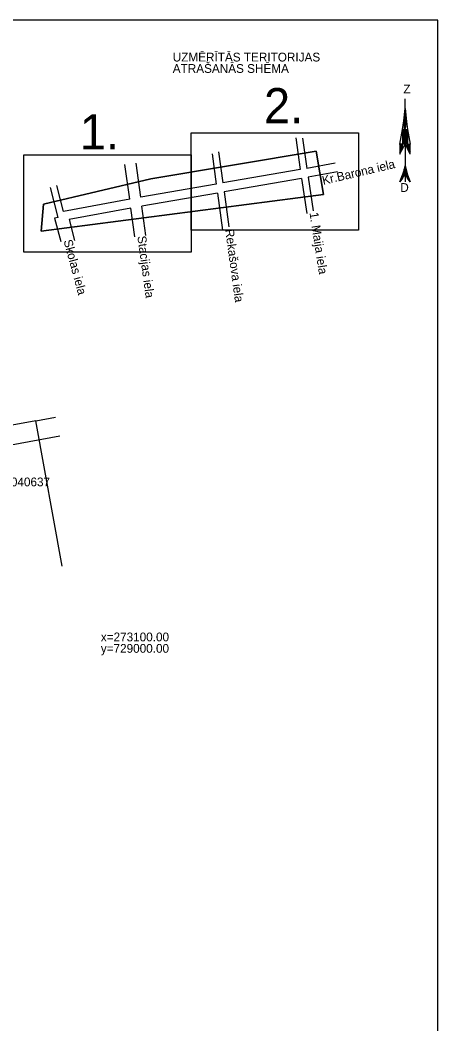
# Model space of a CAD drawing. Extents: x 728492 to 729038, y 272968 to 273171.
# Drawn here: x 728990.8 to 729038.4, y 273056.6 to 273170.9 of the extents above; entities that cross this region are included whole.
import ezdxf

# ---------------------------------------------------------------- set-up
doc = ezdxf.new("R2010")
doc.units = 0
for name, color, linetype in [('APGR_SARK_####_####_#', 7, 'Continuous'), ('GEOD_KORD_####_TKST_#', 7, 'Continuous'), ('RAMI_PLAN_####_TKST_#', 7, 'Continuous'), ('ROBZ_KADS_####_TKST_#', 7, 'Continuous'), ('ROBZ_UZMR_####_####_#', 7, 'Continuous')]:
    doc.layers.add(name, color=color, linetype=linetype)

msp = doc.modelspace()

# ---------------------------------------------------------------- linework, layer by layer
at = {"layer": 'APGR_SARK_####_####_#'}
msp.add_lwpolyline([(728995.34, 273123.52), (728976.64, 273120.07)], dxfattribs=at)
at = {"layer": 'RAMI_PLAN_####_TKST_#'}
for p, q in [((729034.65, 273160.85), (729034.65, 273161.96)), ((729034.49, 273159.46), (729034.65, 273160.85)), ((729034.6, 273160.47), (729034.69, 273160.38)), ((729034.6, 273160.43), (729034.7, 273160.33)), ((729034.6, 273160.39), (729034.7, 273160.28)), ((729034.61, 273160.55), (729034.68, 273160.48)), ((729034.61, 273160.51), (729034.69, 273160.43)), ((729034.62, 273160.63), (729034.67, 273160.58)), ((729034.62, 273160.59), (729034.68, 273160.53)), ((729034.63, 273160.71), (729034.66, 273160.68)), ((729034.63, 273160.67), (729034.67, 273160.63)), ((729034.64, 273160.79), (729034.65, 273160.78)), ((729034.64, 273160.75), (729034.66, 273160.73)), ((729034.65, 273160.85), (729034.8, 273159.38)), ((729034.37, 273158.45), (729034.49, 273159.46)), ((729034.49, 273159.46), (729034.76, 273159.19)), ((729034.63, 273158.45), (729034.49, 273159.46)), ((729034.5, 273159.54), (729034.78, 273159.26)), ((729034.5, 273159.5), (729034.77, 273159.22)), ((729034.5, 273159.41), (729034.76, 273159.15)), ((729034.51, 273159.62), (729034.79, 273159.34)), ((729034.51, 273159.58), (729034.78, 273159.3)), ((729034.51, 273159.35), (729034.75, 273159.11)), ((729034.52, 273159.74), (729034.79, 273159.48)), ((729034.52, 273159.7), (729034.79, 273159.43)), ((729034.52, 273159.66), (729034.8, 273159.38)), ((729034.52, 273159.3), (729034.74, 273159.07)), ((729034.52, 273159.25), (729034.74, 273159.03)), ((729034.53, 273159.82), (729034.78, 273159.58)), ((729034.53, 273159.78), (729034.78, 273159.53)), ((729034.54, 273159.9), (729034.77, 273159.68)), ((729034.54, 273159.86), (729034.77, 273159.63)), ((729034.55, 273159.98), (729034.76, 273159.78)), ((729034.55, 273159.94), (729034.76, 273159.73)), ((729034.56, 273160.1), (729034.74, 273159.93)), ((729034.56, 273160.06), (729034.75, 273159.88)), ((729034.56, 273160.02), (729034.75, 273159.83)), ((729034.57, 273160.18), (729034.73, 273160.03)), ((729034.57, 273160.14), (729034.74, 273159.98)), ((729034.58, 273160.27), (729034.72, 273160.13)), ((729034.58, 273160.23), (729034.73, 273160.08)), ((729034.59, 273160.35), (729034.71, 273160.23)), ((729034.59, 273160.31), (729034.71, 273160.18)), ((729034.8, 273159.38), (729034.63, 273158.45)), ((729034.8, 273159.38), (729034.92, 273158.45)), ((729034.04, 273156.78), (729034.37, 273158.45)), ((729034.37, 273158.45), (729034.36, 273156.81)), ((729034.37, 273158.43), (729034.39, 273158.45)), ((729034.37, 273158.39), (729034.44, 273158.45)), ((729034.37, 273158.34), (729034.48, 273158.45)), ((729034.37, 273158.3), (729034.52, 273158.45)), ((729034.37, 273158.25), (729034.57, 273158.45)), ((729034.37, 273158.21), (729034.61, 273158.45)), ((729034.63, 273158.45), (729034.37, 273158.45)), ((729034.37, 273158.16), (729034.63, 273158.43)), ((729034.37, 273158.12), (729034.63, 273158.38)), ((729034.37, 273158.07), (729034.63, 273158.34)), ((729034.37, 273158.03), (729034.64, 273158.29)), ((729034.37, 273157.98), (729034.64, 273158.25)), ((729034.37, 273157.94), (729034.64, 273158.2)), ((729034.37, 273157.89), (729034.64, 273158.16)), ((729034.37, 273157.85), (729034.64, 273158.11)), ((729034.53, 273159.2), (729034.73, 273159)), ((729034.54, 273159.14), (729034.72, 273158.96)), ((729034.54, 273159.09), (729034.72, 273158.92)), ((729034.55, 273159.04), (729034.71, 273158.88)), ((729034.56, 273158.99), (729034.7, 273158.84)), ((729034.57, 273158.94), (729034.7, 273158.81)), ((729034.57, 273158.88), (729034.69, 273158.77)), ((729034.58, 273158.83), (729034.68, 273158.73)), ((729034.59, 273158.78), (729034.68, 273158.69)), ((729034.6, 273158.73), (729034.67, 273158.65)), ((729034.6, 273158.68), (729034.66, 273158.62)), ((729034.61, 273158.62), (729034.66, 273158.58)), ((729034.62, 273158.57), (729034.65, 273158.54)), ((729034.62, 273158.52), (729034.64, 273158.5)), ((729034.63, 273158.45), (729034.92, 273158.45)), ((729034.64, 273156.8), (729034.63, 273158.45)), ((729034.63, 273158.44), (729034.91, 273158.16)), ((729034.63, 273158.39), (729034.91, 273158.11)), ((729034.63, 273158.35), (729034.91, 273158.07)), ((729034.64, 273158.3), (729034.91, 273158.02)), ((729034.64, 273158.26), (729034.91, 273157.98)), ((729034.64, 273158.21), (729034.91, 273157.93)), ((729034.64, 273158.17), (729034.91, 273157.89)), ((729034.64, 273158.12), (729034.91, 273157.84)), ((729034.64, 273158.08), (729034.91, 273157.8)), ((729034.66, 273158.45), (729034.91, 273158.2)), ((729034.71, 273158.45), (729034.91, 273158.25)), ((729034.75, 273158.45), (729034.91, 273158.29)), ((729034.8, 273158.45), (729034.92, 273158.33)), ((729034.84, 273158.45), (729034.92, 273158.38)), ((729034.89, 273158.45), (729034.92, 273158.42)), ((729034.92, 273158.45), (729034.91, 273156.8)), ((729034.92, 273158.45), (729035.22, 273156.8)), ((729034.36, 273157.44), (729034.64, 273157.71)), ((729034.36, 273157.4), (729034.64, 273157.67)), ((729034.36, 273157.35), (729034.64, 273157.63)), ((729034.36, 273157.31), (729034.64, 273157.58)), ((729034.36, 273157.26), (729034.64, 273157.54)), ((729034.36, 273157.21), (729034.64, 273157.49)), ((729034.36, 273157.17), (729034.64, 273157.45)), ((729034.36, 273157.12), (729034.64, 273157.4)), ((729034.36, 273157.08), (729034.64, 273157.36)), ((729034.36, 273157.04), (729034.64, 273157.31)), ((729034.36, 273156.99), (729034.64, 273157.27)), ((729034.36, 273156.94), (729034.64, 273157.22)), ((729034.36, 273156.9), (729034.64, 273157.18)), ((729034.36, 273156.85), (729034.64, 273157.14)), ((729034.36, 273156.81), (729034.64, 273157.09)), ((729034.37, 273157.8), (729034.64, 273158.07)), ((729034.37, 273157.76), (729034.64, 273158.03)), ((729034.37, 273157.71), (729034.64, 273157.98)), ((729034.37, 273157.67), (729034.64, 273157.94)), ((729034.37, 273157.62), (729034.64, 273157.89)), ((729034.37, 273157.58), (729034.64, 273157.85)), ((729034.37, 273157.53), (729034.64, 273157.8)), ((729034.37, 273157.49), (729034.64, 273157.76)), ((729034.4, 273156.81), (729034.64, 273157.05)), ((729034.44, 273156.8), (729034.64, 273157)), ((729034.49, 273156.8), (729034.64, 273156.96)), ((729034.64, 273158.03), (729034.91, 273157.75)), ((729034.64, 273157.99), (729034.91, 273157.71)), ((729034.64, 273157.94), (729034.91, 273157.66)), ((729034.64, 273157.89), (729034.91, 273157.62)), ((729034.64, 273157.85), (729034.91, 273157.57)), ((729034.64, 273157.81), (729034.91, 273157.53)), ((729034.64, 273157.76), (729034.91, 273157.48)), ((729034.64, 273157.72), (729034.91, 273157.44)), ((729034.64, 273157.67), (729034.91, 273157.4)), ((729034.64, 273157.62), (729034.91, 273157.35)), ((729034.64, 273157.58), (729034.91, 273157.31)), ((729034.64, 273157.53), (729034.91, 273157.26)), ((729034.64, 273157.49), (729034.91, 273157.22)), ((729034.64, 273157.45), (729034.91, 273157.17)), ((729034.64, 273157.4), (729034.91, 273157.13)), ((729034.64, 273157.35), (729034.91, 273157.08)), ((729034.64, 273157.31), (729034.91, 273157.04)), ((729034.64, 273157.26), (729034.91, 273156.99)), ((729034.64, 273157.22), (729034.91, 273156.95)), ((729034.64, 273157.17), (729034.91, 273156.9)), ((729034.64, 273157.13), (729034.91, 273156.86)), ((729034.64, 273157.08), (729034.91, 273156.81)), ((729034.64, 273157.04), (729034.88, 273156.8)), ((729034.64, 273156.99), (729034.84, 273156.8)), ((729034.64, 273156.95), (729034.79, 273156.8)), ((729034.36, 273156.81), (729034.04, 273156.78)), ((729034.04, 273156.6), (729034.24, 273156.8)), ((729034.04, 273156.55), (729034.29, 273156.8)), ((729034.04, 273156.51), (729034.34, 273156.8)), ((729034.04, 273156.73), (729034.1, 273156.79)), ((729034.04, 273156.68), (729034.14, 273156.79)), ((729034.04, 273156.64), (729034.19, 273156.79)), ((729034.04, 273156.46), (729034.36, 273156.78)), ((729034.04, 273156.78), (729034.06, 273155.66)), ((729034.04, 273156.42), (729034.36, 273156.74)), ((729034.04, 273156.38), (729034.36, 273156.69)), ((729034.05, 273156.33), (729034.36, 273156.65)), ((729034.05, 273156.29), (729034.36, 273156.6)), ((729034.05, 273156.24), (729034.36, 273156.56)), ((729034.05, 273156.2), (729034.36, 273156.51)), ((729034.05, 273156.15), (729034.36, 273156.47)), ((729034.05, 273156.11), (729034.36, 273156.42)), ((729034.05, 273156.07), (729034.36, 273156.38)), ((729034.05, 273156.02), (729034.36, 273156.33)), ((729034.05, 273155.98), (729034.36, 273156.29)), ((729034.05, 273155.93), (729034.35, 273156.23)), ((729034.05, 273155.89), (729034.3, 273156.14)), ((729034.05, 273155.85), (729034.25, 273156.05)), ((729034.05, 273155.8), (729034.21, 273155.95)), ((729034.05, 273155.76), (729034.16, 273155.86)), ((729034.06, 273155.66), (729034.36, 273156.25)), ((729034.36, 273156.81), (729034.64, 273156.8)), ((729034.36, 273156.25), (729034.36, 273156.81)), ((729034.36, 273156.25), (729034.64, 273156.8)), ((729034.53, 273156.8), (729034.64, 273156.91)), ((729034.57, 273156.8), (729034.64, 273156.87)), ((729034.62, 273156.8), (729034.64, 273156.82)), ((729034.64, 273156.9), (729034.75, 273156.8)), ((729034.64, 273156.86), (729034.7, 273156.8)), ((729034.64, 273156.81), (729034.66, 273156.8)), ((729034.64, 273156.8), (729034.64, 273154.34)), ((729034.64, 273156.8), (729034.91, 273156.28)), ((729034.91, 273156.8), (729034.64, 273156.8)), ((729034.91, 273156.28), (729034.91, 273156.8)), ((729034.91, 273156.8), (729035.22, 273156.8)), ((729034.91, 273156.79), (729035.22, 273156.48)), ((729034.91, 273156.75), (729035.22, 273156.44)), ((729034.91, 273156.7), (729035.22, 273156.39)), ((729034.91, 273156.66), (729035.22, 273156.35)), ((729034.91, 273156.61), (729035.22, 273156.3)), ((729034.91, 273156.57), (729035.23, 273156.26)), ((729034.91, 273156.53), (729035.23, 273156.21)), ((729034.91, 273156.48), (729035.23, 273156.16)), ((729034.91, 273156.44), (729035.23, 273156.12)), ((729034.91, 273156.39), (729035.23, 273156.07)), ((729034.91, 273156.35), (729035.23, 273156.03)), ((729034.91, 273156.3), (729035.23, 273155.98)), ((729035.23, 273155.66), (729034.91, 273156.28)), ((729034.94, 273156.23), (729035.23, 273155.94)), ((729034.95, 273156.8), (729035.22, 273156.53)), ((729034.99, 273156.8), (729035.22, 273156.57)), ((729034.99, 273156.14), (729035.23, 273155.89)), ((729035.04, 273156.8), (729035.22, 273156.62)), ((729035.04, 273156.04), (729035.23, 273155.85)), ((729035.08, 273156.8), (729035.22, 273156.66)), ((729035.09, 273155.95), (729035.23, 273155.8)), ((729035.13, 273156.8), (729035.22, 273156.71)), ((729035.13, 273155.85), (729035.23, 273155.76)), ((729035.18, 273156.8), (729035.22, 273156.76)), ((729035.23, 273155.66), (729035.22, 273156.8)), ((729034.05, 273155.71), (729034.11, 273155.77)), ((729035.18, 273155.76), (729035.23, 273155.71)), ((729034.64, 273154.34), (729034.36, 273153.31)), ((729034.37, 273153.37), (729034.65, 273153.64)), ((729034.37, 273153.31), (729034.65, 273153.59)), ((729034.39, 273153.43), (729034.65, 273153.68)), ((729034.41, 273153.49), (729034.65, 273153.73)), ((729034.41, 273153.31), (729034.65, 273153.55)), ((729034.42, 273153.55), (729034.64, 273153.77)), ((729034.44, 273153.61), (729034.64, 273153.82)), ((729034.46, 273153.67), (729034.64, 273153.86)), ((729034.46, 273153.32), (729034.65, 273153.51)), ((729034.47, 273153.73), (729034.64, 273153.9)), ((729034.49, 273153.8), (729034.64, 273153.95)), ((729034.51, 273153.86), (729034.64, 273153.99)), ((729034.52, 273153.92), (729034.64, 273154.04)), ((729034.54, 273153.98), (729034.64, 273154.08)), ((729034.56, 273154.04), (729034.64, 273154.12)), ((729034.57, 273154.1), (729034.64, 273154.17)), ((729034.59, 273154.16), (729034.64, 273154.21)), ((729034.61, 273154.22), (729034.64, 273154.26)), ((729034.62, 273154.29), (729034.64, 273154.3)), ((729034.64, 273154.34), (729034.91, 273153.31)), ((729034.65, 273153.32), (729034.64, 273154.34)), ((729034.64, 273154.26), (729034.66, 273154.24)), ((729034.64, 273154.22), (729034.68, 273154.18)), ((729034.64, 273154.17), (729034.7, 273154.12)), ((729034.64, 273154.13), (729034.71, 273154.05)), ((729034.64, 273154.08), (729034.73, 273153.99)), ((729034.64, 273154.04), (729034.75, 273153.93)), ((729034.64, 273153.99), (729034.76, 273153.87)), ((729034.64, 273153.94), (729034.78, 273153.81)), ((729034.64, 273153.9), (729034.8, 273153.75)), ((729034.64, 273153.85), (729034.81, 273153.68)), ((729034.64, 273153.81), (729034.83, 273153.62)), ((729034.64, 273153.76), (729034.85, 273153.56)), ((729034.65, 273153.72), (729034.86, 273153.5)), ((729034.65, 273153.67), (729034.88, 273153.44)), ((729034.65, 273153.63), (729034.89, 273153.38)), ((729034.65, 273153.58), (729034.91, 273153.32)), ((729034.65, 273153.54), (729034.87, 273153.31)), ((729034.04, 273152.5), (729034.36, 273153.31)), ((729034.36, 273152.92), (729034.04, 273152.5)), ((729034.07, 273152.59), (729034.21, 273152.72)), ((729034.1, 273152.66), (729034.36, 273152.92)), ((729034.13, 273152.73), (729034.36, 273152.96)), ((729034.16, 273152.81), (729034.36, 273153.01)), ((729034.19, 273152.88), (729034.36, 273153.05)), ((729034.22, 273152.95), (729034.36, 273153.1)), ((729034.25, 273153.03), (729034.36, 273153.14)), ((729034.28, 273153.1), (729034.36, 273153.18)), ((729034.31, 273153.18), (729034.36, 273153.23)), ((729034.34, 273153.25), (729034.36, 273153.27)), ((729034.36, 273153.31), (729034.65, 273153.32)), ((729034.36, 273152.92), (729034.65, 273153.32)), ((729034.36, 273153.31), (729034.36, 273152.92)), ((729034.5, 273153.32), (729034.65, 273153.46)), ((729034.55, 273153.32), (729034.65, 273153.42)), ((729034.6, 273153.32), (729034.65, 273153.37)), ((729034.65, 273153.32), (729034.64, 273152.49)), ((729034.65, 273153.49), (729034.82, 273153.32)), ((729034.65, 273153.44), (729034.78, 273153.32)), ((729034.65, 273153.4), (729034.73, 273153.32)), ((729034.65, 273153.35), (729034.69, 273153.32)), ((729034.91, 273153.31), (729034.65, 273153.32)), ((729034.65, 273153.32), (729034.91, 273152.92)), ((729034.91, 273153.31), (729035.22, 273152.49)), ((729034.91, 273152.92), (729034.91, 273153.31)), ((729034.91, 273153.26), (729034.95, 273153.22)), ((729034.91, 273153.21), (729034.97, 273153.15)), ((729034.91, 273153.17), (729035, 273153.08)), ((729034.91, 273153.12), (729035.03, 273153.01)), ((729034.91, 273153.08), (729035.05, 273152.94)), ((729034.91, 273153.03), (729035.08, 273152.86)), ((729034.91, 273152.99), (729035.11, 273152.79)), ((729034.91, 273152.94), (729035.13, 273152.72)), ((729035.22, 273152.49), (729034.91, 273152.92)), ((729034.97, 273152.84), (729035.16, 273152.65)), ((729035.08, 273152.69), (729035.19, 273152.58)), ((728995.13, 273148.45), (728994.74, 273148.35))]:
    msp.add_line(p, q, dxfattribs=at)
for points in [[(728765.31, 273170.93), (728765.31, 272986.9), (729038.38, 272986.9), (729038.38, 273170.93)], [(729010.28, 273158.09), (729029.34, 273158.09), (729029.34, 273147), (729010.28, 273147)], [(728993.46, 273149.97), (729005.69, 273152.83), (729024.51, 273156.01), (729025.34, 273151.06), (728993.21, 273146.88)], [(728991.22, 273155.56), (729010.28, 273155.56), (729010.28, 273144.47), (728991.22, 273144.47)]]:
    msp.add_lwpolyline(points, close=True, dxfattribs=at)
for points in [[(729022.2, 273157.53), (729022.7, 273153.9)], [(729022.98, 273157.47), (729023.46, 273154.03)], [(728993.21, 273146.88), (729025.34, 273151.06), (729024.51, 273156.01), (729005.69, 273152.83), (728993.46, 273149.97), (728993.21, 273146.88)], [(729013.4, 273155.91), (729013.89, 273152.37)], [(729012.66, 273155.69), (729013.13, 273152.24)], [(729003.29, 273150.52), (729002.75, 273154.49)], [(729004.55, 273150.74), (729004.02, 273154.61)], [(729022.7, 273153.9), (729013.89, 273152.37)], [(729026.68, 273154.63), (729023.46, 273154.03)], [(729026.96, 273153.64), (729023.61, 273153.02)], [(729022.85, 273152.88), (729014.03, 273151.35)], [(729022.85, 273152.88), (729023.46, 273148.91)], [(729023.61, 273153.02), (729024.19, 273149.21)], [(728995.13, 273148.45), (728994.27, 273151.84)], [(728995.75, 273149.12), (728995, 273152.09)], [(729013.13, 273152.24), (729004.55, 273150.74)], [(729013.27, 273151.22), (729004.68, 273149.73)], [(729013.27, 273151.22), (729013.85, 273147.01)], [(729014.03, 273151.35), (729014.58, 273147.36)], [(729003.29, 273150.52), (728995.75, 273149.12)], [(729003.42, 273149.5), (728996.38, 273148.2)], [(729003.87, 273146.24), (729003.42, 273149.5)], [(729005.14, 273146.37), (729004.68, 273149.73)], [(728994.74, 273148.35), (728995.46, 273145.71)], [(728996.38, 273148.2), (728997.02, 273145.81)]]:
    msp.add_lwpolyline(points, dxfattribs=at)
at = {"layer": 'ROBZ_UZMR_####_####_#'}
for p, q in [((728992.59, 273125.28), (728980.58, 273123.04)), ((728992.59, 273125.28), (728994.83, 273125.69)), ((728995.6, 273108.71), (728992.59, 273125.28))]:
    msp.add_line(p, q, dxfattribs=at)

# ---------------------------------------------------------------- texts
at = {"layer": 'GEOD_KORD_####_TKST_#'}
for s, p in [('x=273100.00', (729000, 273100.15)), ('y=729000.00', (729000, 273098.85))]:
    msp.add_text(s, height=1, dxfattribs=at).set_placement(p)
at = {"layer": 'RAMI_PLAN_####_TKST_#'}
for s, rotation, p in [('UZMĒRĪTĀS TERITORIJAS ', 359.9999, (729008.19, 273166.21)), ('ATRAŠANĀS SHĒMA', 359.9999, (729008.19, 273164.91)), ('Z', 359.9999, (729034.45, 273162.58)), ('Kr.Barona iela', 13.1935, (729025.33, 273152.15)), ('D', 359.9999, (729034.1, 273151.35)), ('1. Maija iela', 278.7513, (729023.76, 273148.96)), ('Rekašova iela', 277.8071, (729014.15, 273147.05)), ('Skolas iela', 285.1109, (728995.75, 273145.78)), ('Stacijas iela', 277.7218, (729004.16, 273146.28))]:
    msp.add_text(s, height=1, rotation=rotation, dxfattribs=at).set_placement(p)
for s, p in [('2.', (729018.58, 273159.18)), ('1.', (728997.62, 273156.2))]:
    msp.add_text(s, height=4, dxfattribs=at).set_placement(p)
at = {"layer": 'ROBZ_KADS_####_TKST_#'}
msp.add_text('68010040637', height=1, dxfattribs=at).set_placement((728986.04, 273117.81))

doc.saveas('drawing.dxf')
